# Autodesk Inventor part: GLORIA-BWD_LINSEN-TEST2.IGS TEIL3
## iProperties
Created: 2005-04
Part Number: GLORIA-BWD_LINSEN-TEST2.IGS TEIL3
Document SubType Name: Modeling
Designer: Nordmeyer
Manufacturer: Standard
Standards Organization: Custom
Author: Nordmeyer
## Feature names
1. Erst1
